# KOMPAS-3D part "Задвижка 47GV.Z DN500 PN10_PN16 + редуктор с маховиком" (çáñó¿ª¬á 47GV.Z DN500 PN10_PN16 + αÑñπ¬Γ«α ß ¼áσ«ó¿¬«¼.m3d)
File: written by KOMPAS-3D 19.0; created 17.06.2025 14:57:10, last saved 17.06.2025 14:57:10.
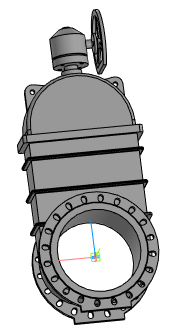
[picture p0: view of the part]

Document properties: Полное имя файла: Задвижка 47GV.Z DN500 PN10_PN16 + редуктор с маховиком.a3d

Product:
- Part/product: Задвижка 47GV.Z DN500 PN10_PN16 + редуктор с маховиком
    Масса: 1254.99

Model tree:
1. Операция без истории:1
